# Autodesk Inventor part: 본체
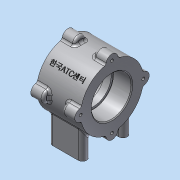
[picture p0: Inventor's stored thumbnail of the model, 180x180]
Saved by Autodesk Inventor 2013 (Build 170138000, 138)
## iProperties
Created: 2015-03
Part Number: 본체
Material: 알루미늄 6061
Document SubType Name: Modeling
Designer: dgall
Density: 1 g/cm^3
Author: dgall
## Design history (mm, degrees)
sketch "스케치1"
  geometry: C1 r 37 at (0, 0); 1 further point
  constraints: 1 centre point, 1 coincident
  dimensions: "d0" = 74 diameter of C1
extrude "돌출1" new body sketch "스케치1" distance "d2" = 52; taper "d3" = 0 deg
sketch "스케치2"
  geometry: L1 (-7, 37)-(-7, 36.332); L2 (7, 37)-(7, 36.332); A1 r 37 centre (0, 0) between (0, 37) and (-7, 36.332) reference; A2 r 7 centre (0, 37) between (7, 37) and (-7, 37)
  constraints: 5 point on circle, 4 end point, 2 tangent, 1 centre point, 1 parallel, 1 vertical, 1 vertical alignment
  dimensions: "d4" = 7 radius of A2
extrude "돌출2" join sketch "스케치2" distance "d6" = 15; taper "d7" = 0 deg
fillet "모깎기1" dims "d8" = 3
fillet "모깎기2" dims "d9" = 3
fillet "모깎기3" dims "d10" = 3
fillet "모깎기4" dims "d11" = 3
sketch "스케치3"
  geometry: A1 r 37 centre (0, 0) between (-9.104, 35.863) and (9.104, 35.863) reference; A2 r 3 centre (-9.842, 38.77) between (-9.104, 35.863) and (-6.889, 38.239) reference; A3 r 7 centre (0, 37) between (6.889, 38.239) and (-6.889, 38.239) reference; A4 r 3 centre (9.842, 38.77) between (6.889, 38.239) and (9.104, 35.863) reference
extrude "돌출3" join sketch "스케치3" distance "d15" = 15; taper "d16" = 0 deg
fillet "모깎기5" dims "d17" = 3
fillet "모깎기6" dims "d18" = 3
sketch "스케치4"
  geometry: L1 (-29, 41)-(-29, 11); L2 (-19, 11)-(-19, 41); L3 (19, 41)-(19, 11); L4 (29, 11)-(29, 41); L5 (-37, 18)-(-37, 34) reference; L6 (37, 18)-(37, 34) reference; L7 (-29, 26)-(29, 26); A1 r 5 centre (-24, 11) between (-29, 11) and (-19, 11); A2 r 5 centre (-24, 41) between (-19, 41) and (-29, 41); A3 r 5 centre (24, 11) between (19, 11) and (29, 11); A4 r 5 centre (24, 41) between (29, 41) and (19, 41); 3 further points
  constraints: 10 end point, 8 point on circle, 8 tangent, 4 centre point, 4 midpoint, 3 horizontal alignment, 3 parallel, 1 equal radius, 1 vertical, 1 vertical alignment
  dimensions: "d22" = 48 distance of A3.centre A1.centre; "d24" = 10 distance between parallel lines of L1 L2; "d25" = 40 dimension on A1 A2
extrude "돌출4" join sketch "스케치4" distance "d26" = 56; taper "d27" = 0 deg
hole "구멍1" diameter "d30" = 3.459; stored, may be unused: countersink angle "d34" = 90 deg, drill point angle "d36" = 118 deg; dims "d28" = 10, "d29" = 10, "d31" = 8, "d32" = 4, "d33" = 2, "d35" = 11
node "작업 평면2"
hole "구멍2" diameter "d42" = 4.134; stored, may be unused: countersink angle "d46" = 90 deg, drill point angle "d48" = 118 deg; dims "d40" = 10, "d41" = 10, "d43" = 6, "d44" = 4, "d45" = 2, "d47" = 8
hole "구멍3" diameter "d51" = 4.134; stored, may be unused: countersink angle "d55" = 90 deg, drill point angle "d57" = 118 deg; dims "d49" = 10, "d50" = 10, "d52" = 6, "d53" = 4, "d54" = 2, "d56" = 8
hole "구멍4" diameter "d60" = 4.134; stored, may be unused: countersink angle "d64" = 90 deg, drill point angle "d66" = 118 deg; dims "d58" = 10, "d59" = 10, "d61" = 6, "d62" = 4, "d63" = 2, "d65" = 8
hole "구멍5" diameter "d69" = 4.134; stored, may be unused: countersink angle "d73" = 90 deg, drill point angle "d75" = 118 deg; dims "d67" = 10, "d68" = 10, "d70" = 6, "d71" = 4, "d72" = 2, "d74" = 8
fillet "모깎기7" dims "d76" = 3
hole "구멍6" diameter "d79" = 42; stored, may be unused: countersink angle "d83" = 90 deg, drill point angle "d85" = 0 deg; dims "d77" = 10, "d78" = 10, "d80" = 6, "d81" = 47, "d82" = 22, "d84" = 8
hole "구멍7" diameter "d88" = 47; stored, may be unused: countersink angle "d92" = 90 deg, drill point angle "d94" = 0 deg; dims "d86" = 10, "d87" = 10, "d89" = 6, "d90" = 47, "d91" = 22, "d93" = 22
fillet "모깎기8" dims "d95" = 0.3
chamfer "모따기1" distance "d96" = 1; stored, may be unused: second distance "d97" = 2, angle "d98" = 45 deg
node "작업 평면4"
  node "작업 평면3"
sketch "스케치5"
  geometry: L1 (-18.921, 0)-(18.921, 0) reference; L2 (18.921, 52)-(-18.921, 52) reference; 3 further points
  constraints: 1 midpoint, 1 vertical alignment, 1 other
  dimensions: "d100" = 26 distance from line of L2 point (0, 26)
feature "엠보싱1" sketch "스케치5" dims "d10" = 3, "d101" = 0.5, "d102" = 0
node "솔리드1"
pattern_circular "원형 패턴1" dims "d13" = 360 deg
pattern_circular "원형 패턴2" dims "d20" = 360 deg
pattern_circular "원형 패턴3" dims angle "d38" = 360 deg
mirror "대칭1"
node "작업축1"
other parameters: "d99" = 45 deg
